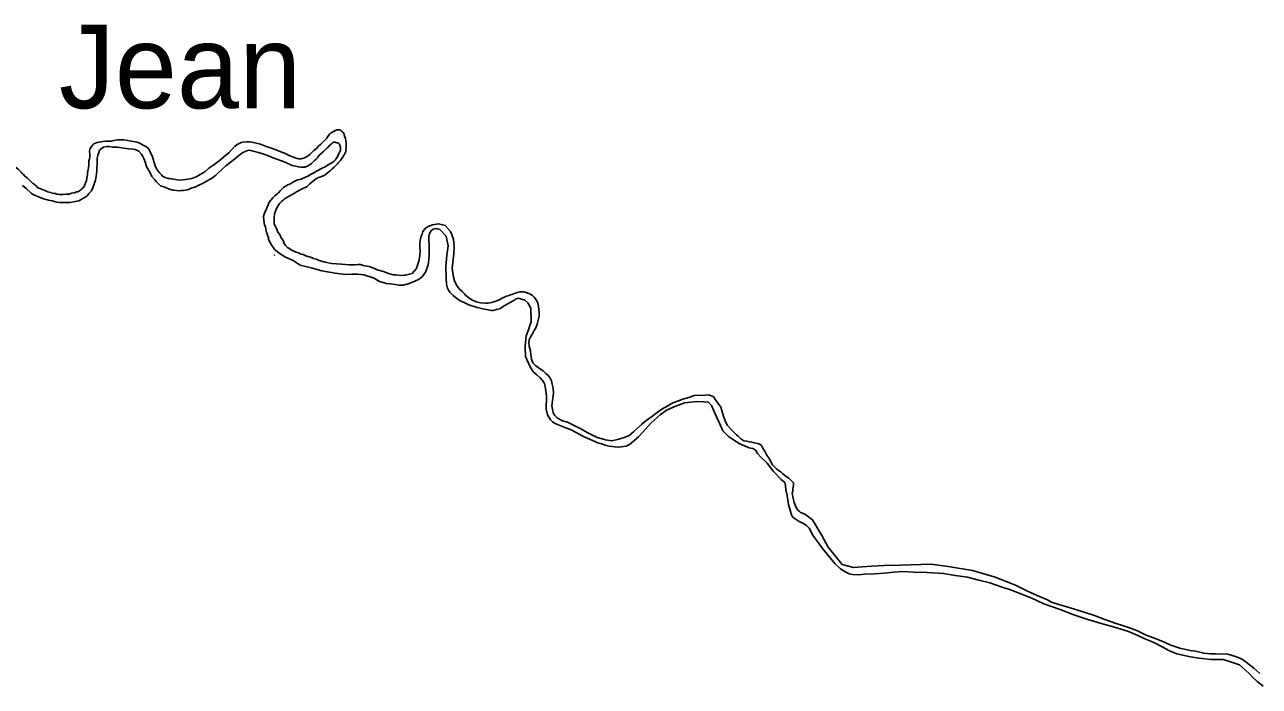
# Model space of a CAD drawing. Extents: x -83719 to 153526, y -11835 to 11446.
# Drawn here: x -3827.5 to -3567.5, y -157.2 to -17.9 of the extents above; entities that cross this region are included whole.
import ezdxf

# ---------------------------------------------------------------- set-up
doc = ezdxf.new("R2010")
doc.units = 0
doc.layers.add('Level 9', color=7, linetype='Continuous')

msp = doc.modelspace()

# ---------------------------------------------------------------- linework, layer by layer
at = {"layer": 'Level 9'}
for points in [[(-3761.85, -40.05), (-3761.95, -40.1), (-3762.21, -40.2), (-3762.61, -40.41), (-3762.88, -40.61), (-3763.17, -40.81), (-3763.34, -40.95), (-3763.7, -41.45), (-3763.93, -41.79), (-3764.19, -42.06), (-3764.59, -42.47), (-3764.95, -42.84), (-3765.25, -43.14), (-3765.65, -43.45), (-3766.18, -44.02), (-3766.66, -44.39)], [(-3761.85, -40.05), (-3761.64, -40), (-3761.41, -40), (-3761.19, -40.04), (-3760.99, -40.13), (-3760.79, -40.27), (-3760.57, -40.45), (-3760.47, -40.61), (-3760.33, -40.82), (-3760.13, -41.49), (-3760, -41.85), (-3759.89, -42.26), (-3759.85, -42.76), (-3759.84, -43.45), (-3759.85, -43.85), (-3759.9, -44.14), (-3759.92, -44.56), (-3759.99, -44.72), (-3760.11, -45.08), (-3760.31, -45.37)], [(-3773.66, -46.51), (-3775.23, -45.9), (-3776.41, -45.41), (-3777.18, -45.16), (-3778.28, -44.77), (-3779.39, -44.48), (-3779.92, -44.35), (-3780.22, -44.32), (-3780.49, -44.36), (-3780.76, -44.43), (-3781.09, -44.57), (-3781.19, -44.64), (-3781.45, -44.74), (-3781.79, -44.91), (-3781.89, -45.01), (-3782.12, -45.15), (-3783.34, -46.2), (-3783.97, -46.71), (-3785.19, -47.62), (-3785.92, -48.33), (-3787.31, -49.55), (-3788.23, -50.26), (-3789.26, -50.81), (-3789.96, -51.25), (-3791.02, -51.76), (-3791.52, -52), (-3792.25, -52.25), (-3793.25, -52.66), (-3794.11, -52.8), (-3794.68, -52.81), (-3795.08, -52.85), (-3795.58, -52.82), (-3796.35, -52.7), (-3797.25, -52.47), (-3797.99, -52.12), (-3798.96, -51.79), (-3799.84, -50.87), (-3800.21, -50.47), (-3800.76, -49.85), (-3801.03, -49.18), (-3801.34, -48.69), (-3801.47, -48.45), (-3801.78, -47.99), (-3801.95, -47.53), (-3802.19, -46.76), (-3802.47, -46.03), (-3802.74, -45.5), (-3802.91, -45.14), (-3803.52, -44.54), (-3804.29, -44.15), (-3804.69, -44.12), (-3805.59, -44.03), (-3806.7, -43.85), (-3808, -43.7), (-3809.04, -43.64), (-3809.74, -43.55), (-3810.14, -43.56), (-3810.91, -43.7), (-3811.24, -43.87), (-3811.37, -43.94), (-3811.63, -44.14), (-3811.77, -44.28), (-3811.96, -44.81), (-3812.15, -45.41), (-3812.25, -45.98), (-3812.31, -46.75), (-3812.32, -48.52), (-3812.44, -49.39), (-3812.66, -50.63), (-3813.05, -51.8), (-3813.18, -52.23), (-3813.47, -52.84), (-3814, -53.41), (-3814.33, -53.85), (-3814.69, -54.15), (-3815.06, -54.36), (-3815.49, -54.6), (-3816.12, -54.94), (-3816.52, -55.01), (-3817.18, -55.15), (-3817.98, -55.3), (-3818.72, -55.3), (-3819.52, -55.31), (-3820.19, -55.32), (-3820.75, -55.26), (-3821.79, -54.97), (-3822.53, -54.82), (-3823.57, -54.53), (-3824.07, -54.34), (-3824.61, -54.14), (-3825.24, -53.85), (-3825.68, -53.69), (-3826.15, -53.33), (-3827.2, -52.37), (-3828, -51.75)], [(-3800.08, -47.6), (-3800.7, -45.51), (-3801.08, -44.75), (-3801.22, -44.28), (-3801.63, -43.82), (-3802.03, -43.52), (-3802.7, -43.16), (-3803.31, -42.84), (-3803.84, -42.64), (-3804.68, -42.45), (-3805.88, -42.24), (-3806.68, -42.14), (-3807.32, -42.09), (-3808.02, -42.13), (-3808.75, -42.24), (-3809.32, -42.38), (-3809.59, -42.38), (-3810.49, -42.39), (-3811.05, -42.47), (-3811.49, -42.57), (-3811.95, -42.61), (-3812.29, -42.71), (-3812.98, -42.96), (-3813.21, -43.16), (-3813.48, -43.56), (-3813.74, -43.93), (-3813.87, -44.53), (-3813.79, -45.2), (-3813.85, -45.7), (-3813.92, -46.1), (-3814.01, -46.54), (-3814.03, -47.41), (-3814.13, -47.94), (-3814.16, -48.38), (-3814.32, -49.04), (-3814.31, -49.48), (-3814.44, -50.18), (-3814.53, -50.72), (-3814.72, -51.25), (-3814.86, -51.55), (-3815.05, -51.99), (-3815.41, -52.39), (-3815.64, -52.6), (-3816.01, -52.84), (-3816.24, -53.01), (-3816.44, -53.11), (-3816.64, -53.11), (-3817.04, -53.28), (-3817.2, -53.32), (-3817.67, -53.39), (-3818.2, -53.56), (-3818.8, -53.6), (-3819.5, -53.61), (-3819.74, -53.62), (-3820.31, -53.62), (-3820.74, -53.56), (-3821.08, -53.46), (-3821.41, -53.4), (-3821.71, -53.37), (-3821.98, -53.28), (-3822.05, -53.24), (-3822.72, -53.05), (-3822.82, -52.99)], [(-3773.24, -44.77), (-3775.12, -44), (-3776.46, -43.58), (-3777.87, -43.06), (-3778.77, -42.84), (-3779.68, -42.58), (-3780.21, -42.56), (-3780.68, -42.53), (-3781.58, -42.61), (-3781.98, -42.71), (-3782.48, -42.95), (-3783.27, -43.46), (-3784.46, -44.81), (-3785.22, -45.42), (-3786.61, -46.54), (-3787.67, -47.42), (-3788.79, -48.1), (-3789.62, -48.84), (-3790.55, -49.46), (-3791.31, -49.83), (-3792.31, -50.24), (-3793.21, -50.42), (-3794.14, -50.53), (-3794.97, -50.61), (-3796.18, -50.43), (-3796.64, -50.36), (-3796.98, -50.3), (-3797.33, -50.24)], [(-3761.03, -44.26), (-3761, -43.72), (-3761.07, -43.56), (-3761.07, -43.46), (-3761.18, -43.23), (-3761.28, -42.99), (-3761.31, -42.96), (-3761.45, -42.86), (-3761.55, -42.76), (-3761.78, -42.73), (-3762.02, -42.67), (-3762.19, -42.64), (-3762.35, -42.64), (-3762.52, -42.64), (-3762.72, -42.74), (-3762.95, -42.95), (-3763.21, -43.18), (-3763.35, -43.35), (-3763.64, -43.66), (-3763.94, -43.96), (-3764.17, -44.16), (-3764.57, -44.53), (-3764.8, -44.74), (-3764.96, -44.91), (-3765.36, -45.24), (-3765.52, -45.45), (-3765.79, -45.75), (-3765.85, -45.88), (-3766.08, -46.12), (-3766.18, -46.22), (-3766.51, -46.49), (-3766.61, -46.63), (-3767.01, -46.97), (-3767.14, -47.1), (-3767.44, -47.31), (-3767.7, -47.48), (-3767.86, -47.58)], [(-3770.84, -47.6), (-3771.18, -47.52), (-3771.51, -47.42), (-3771.81, -47.26), (-3771.88, -47.19), (-3772.22, -47.1), (-3772.38, -47), (-3772.92, -46.77), (-3773.22, -46.64), (-3773.46, -46.58), (-3773.66, -46.51)], [(-3771.12, -45.72), (-3771.16, -45.72), (-3771.46, -45.59), (-3771.67, -45.49), (-3772.14, -45.26), (-3772.27, -45.23), (-3772.57, -45.07), (-3772.81, -44.94), (-3773.24, -44.77)], [(-3766.66, -44.39), (-3766.98, -44.73), (-3767.42, -45.15), (-3767.85, -45.48), (-3768.31, -45.77), (-3768.6, -45.9), (-3768.85, -45.96), (-3769.34, -46.11), (-3769.64, -46.12), (-3769.86, -46.11), (-3770.16, -46.06), (-3770.56, -45.92), (-3771.12, -45.72)], [(-3760.89, -46.26), (-3761.13, -46.55), (-3761.45, -46.92), (-3761.64, -47.15), (-3762.01, -47.5), (-3762.35, -47.85), (-3762.79, -48.26), (-3763.22, -48.66), (-3763.53, -48.92)], [(-3763.29, -47.21), (-3763, -47.02), (-3762.8, -46.92), (-3762.57, -46.75), (-3762.37, -46.61), (-3762.11, -46.31), (-3761.91, -46.04), (-3761.85, -45.97), (-3761.62, -45.57), (-3761.46, -45.16), (-3761.23, -44.73), (-3761.13, -44.63), (-3761.1, -44.46), (-3761.03, -44.26)], [(-3760.89, -46.26), (-3760.78, -46.02), (-3760.38, -45.48), (-3760.31, -45.37)], [(-3825.5, -51.53), (-3825.87, -51.22), (-3826.24, -50.89), (-3826.45, -50.69), (-3826.62, -50.56), (-3827.05, -50.13), (-3827.49, -49.77), (-3827.8, -49.41), (-3827.97, -49.21), (-3828.17, -49.11), (-3828.44, -48.85), (-3828.44, -48.82), (-3828.88, -48.35), (-3829.21, -48.09), (-3829.58, -47.82)], [(-3800.08, -47.6), (-3800.02, -47.76), (-3799.93, -47.94), (-3799.72, -48.33), (-3799.45, -48.72), (-3799.05, -49.11), (-3798.75, -49.53), (-3798.42, -49.84), (-3797.98, -50.03), (-3797.33, -50.24)], [(-3770.84, -47.6), (-3770.42, -47.69), (-3769.9, -47.83), (-3769.39, -47.91), (-3769.01, -47.88), (-3768.61, -47.86), (-3768.49, -47.83), (-3768.31, -47.78), (-3767.86, -47.58)], [(-3770.27, -53.06), (-3770.01, -52.91), (-3769.22, -52.53), (-3768.05, -51.95), (-3767.53, -51.44), (-3767.06, -51.04), (-3766.27, -50.43), (-3766.17, -50.33), (-3766.04, -50.26), (-3765.77, -50.15), (-3765.71, -50.09), (-3765.37, -49.98), (-3764.81, -49.81), (-3764.31, -49.54), (-3763.75, -49.1), (-3763.53, -48.92)], [(-3763.29, -47.21), (-3763.74, -47.49), (-3764.28, -47.79), (-3764.86, -48.08), (-3765.3, -48.32), (-3765.66, -48.5), (-3766.09, -48.74), (-3766.76, -49.14), (-3767.2, -49.35), (-3767.56, -49.57)], [(-3825.5, -51.53), (-3825.13, -51.8), (-3824.97, -51.99), (-3824.6, -52.27), (-3824.29, -52.38), (-3824.02, -52.52), (-3823.62, -52.68), (-3823.4, -52.73)], [(-3774.9, -65.25), (-3774.95, -65.18), (-3775.01, -65.05), (-3775.25, -64.65), (-3775.52, -64.39), (-3775.8, -63.92), (-3775.97, -63.52), (-3776.17, -63.06), (-3776.21, -62.73), (-3776.42, -62.2), (-3776.56, -61.7), (-3776.66, -61.43), (-3776.73, -60.87), (-3776.84, -60.47), (-3777.01, -60.07), (-3777.19, -59.04), (-3777.23, -58.27), (-3777, -57.57), (-3776.61, -56.69), (-3776.26, -55.79), (-3776.03, -55.28), (-3775.3, -54.37), (-3774.84, -53.94), (-3774.34, -53.53), (-3774.11, -53.26), (-3773.75, -52.89), (-3773.39, -52.52), (-3773.03, -52.18), (-3772.13, -51.6), (-3771.4, -51.29), (-3771.1, -51.05), (-3770.47, -50.75), (-3770.07, -50.57), (-3769.57, -50.47), (-3769.14, -50.33), (-3768.41, -50.02), (-3767.91, -49.81), (-3767.56, -49.57)], [(-3822.82, -52.99), (-3823.29, -52.79), (-3823.4, -52.73)], [(-3770.27, -53.06), (-3770.7, -53.34), (-3771.24, -53.65), (-3771.97, -54.05), (-3772.5, -54.32), (-3772.84, -54.58), (-3773.12, -54.8), (-3773.45, -55.1), (-3773.67, -55.32), (-3773.85, -55.55)], [(-3765.51, -67.53), (-3766.11, -67.28), (-3766.68, -67.12), (-3767.15, -66.92), (-3767.65, -66.79), (-3768.32, -66.53), (-3768.49, -66.47), (-3768.89, -66.27), (-3769.33, -66.18), (-3769.9, -65.92), (-3770.33, -65.79), (-3770.84, -65.6), (-3770.94, -65.5), (-3771.34, -65.34), (-3771.91, -64.94), (-3772.18, -64.78), (-3772.59, -64.38), (-3772.86, -63.95), (-3773.13, -63.36), (-3773.57, -62.63), (-3773.71, -62.2), (-3774.12, -61.67), (-3774.29, -61.4), (-3774.46, -60.94), (-3774.73, -60.41), (-3774.97, -59.88), (-3775.01, -59.21), (-3775.02, -58.58), (-3774.9, -57.74), (-3774.61, -56.74), (-3774.25, -56.13), (-3773.85, -55.55)], [(-3721.33, -84.88), (-3721.27, -84.28), (-3720.95, -83.57), (-3720.43, -82.73), (-3720.24, -82.26), (-3719.82, -81.58), (-3719.59, -80.94), (-3719.15, -79.3), (-3719.2, -78.53), (-3719.25, -77.76), (-3719.36, -76.79), (-3719.5, -76.33), (-3719.95, -75.6), (-3720.26, -75.24), (-3720.6, -74.88), (-3721.17, -74.58), (-3721.54, -74.39), (-3722.11, -74.2), (-3722.51, -74.14), (-3723.18, -74.12), (-3723.54, -74.19), (-3724.04, -74.33), (-3724.73, -74.61), (-3725.4, -74.86), (-3725.53, -74.89), (-3726.06, -75.07), (-3726.99, -75.45), (-3727.61, -75.83), (-3728.08, -76.04), (-3728.71, -76.28), (-3729.21, -76.36), (-3729.9, -76.51), (-3730.54, -76.52), (-3731.44, -76.47), (-3732.48, -76.25), (-3733.35, -75.83), (-3734.06, -75.34), (-3734.63, -74.92), (-3734.94, -74.55), (-3735.38, -74.09), (-3735.99, -73.57), (-3736.47, -72.94), (-3736.81, -72.31), (-3737.05, -71.82), (-3737.2, -71.02), (-3737.5, -69.15), (-3737.18, -66.17), (-3737.11, -64.56), (-3737.2, -63.03), (-3737.86, -61.43), (-3738.98, -60.15), (-3740.42, -59.81), (-3741.62, -60.03), (-3742.58, -60.38), (-3743.17, -60.79), (-3743.66, -61.43), (-3743.85, -61.97), (-3744.01, -62.41), (-3744.26, -63.35), (-3744.35, -63.99), (-3744.3, -64.89), (-3744.26, -65.42), (-3744.31, -66.56), (-3744.52, -67.7), (-3744.78, -68.51), (-3745.03, -69.21), (-3745.49, -69.82), (-3745.95, -70.26), (-3747.31, -70.62), (-3747.64, -70.66), (-3748.41, -70.71), (-3749.31, -70.59), (-3749.88, -70.53), (-3750.95, -70.28), (-3751.96, -69.86), (-3753.3, -69.49), (-3754.04, -69.17), (-3755.01, -68.81), (-3756.25, -68.57), (-3756.78, -68.38), (-3757.38, -68.35), (-3757.99, -68.42)], [(-3721.44, -82.14), (-3721.15, -81.24), (-3720.9, -80.46), (-3720.95, -77.59), (-3721.54, -76.43), (-3722.18, -75.87), (-3723.62, -75.5), (-3724.15, -75.71), (-3724.41, -75.91), (-3725.54, -76.56), (-3726.39, -77.01), (-3726.89, -77.29), (-3727.35, -77.63), (-3727.91, -77.81), (-3728.91, -78.09), (-3729.28, -78.07), (-3730.28, -77.88), (-3731.08, -77.7), (-3732.26, -77.45), (-3734, -76.91), (-3734.87, -76.49), (-3735.81, -76.01), (-3736.49, -75.55), (-3737.3, -74.93), (-3738.01, -74.24), (-3738.29, -73.78), (-3738.49, -73.34), (-3738.71, -72.51), (-3738.79, -71.31), (-3738.84, -68.77), (-3738.61, -66.43), (-3738.38, -64.42), (-3738.78, -62.39), (-3740.07, -61), (-3740.64, -60.85), (-3740.94, -60.82), (-3741.54, -60.96), (-3741.87, -61.2), (-3742.19, -61.61), (-3742.22, -61.81), (-3742.35, -62.15), (-3742.41, -62.38), (-3742.44, -62.82), (-3742.34, -64.82), (-3742.35, -66.22), (-3742.43, -67.43), (-3742.58, -68.43), (-3743.15, -70.01), (-3743.84, -71), (-3744.63, -71.51), (-3745.85, -72.1), (-3746.74, -72.45), (-3747.84, -72.74), (-3748.71, -72.75), (-3749.54, -72.63), (-3750.55, -72.48), (-3751.35, -72.36), (-3752.82, -71.95), (-3753.19, -71.72), (-3753.97, -71.27), (-3754.77, -70.98), (-3755.51, -70.79), (-3756.11, -70.57), (-3756.68, -70.48), (-3757.48, -70.43), (-3758.62, -70.41)], [(-3775, -66.47), (-3774.93, -66.42)], [(-3774.93, -66.42), (-3774.87, -66.38)], [(-3758.62, -70.41), (-3759.91, -70.46), (-3762.14, -70.2), (-3764.94, -69.73), (-3767.22, -69.06), (-3769.51, -68.49), (-3771.01, -67.55), (-3772.62, -66.83), (-3773.76, -66.15), (-3774.9, -65.25)], [(-3757.99, -68.42), (-3759.13, -68.43), (-3760.84, -68.28), (-3762.92, -68.18), (-3764.27, -67.92), (-3765.51, -67.53)], [(-3595.09, -145.69), (-3597.98, -144.8), (-3600.52, -144.08), (-3603.64, -143.16), (-3606.59, -142.21), (-3609.44, -141.06), (-3612.86, -139.84), (-3615.28, -138.75), (-3617.73, -137.75), (-3619.92, -136.92), (-3621.66, -136.38), (-3624.24, -135.46), (-3626.59, -134.86), (-3629, -134.24), (-3631.54, -133.88), (-3634.01, -133.45), (-3637.45, -133.28), (-3640.32, -133.16), (-3642.49, -133.06), (-3644.45, -133.17), (-3646.52, -133.37), (-3648.45, -133.57), (-3650.68, -133.64), (-3651.88, -133.73), (-3653.18, -133.68), (-3653.88, -133.56), (-3654.32, -133.33), (-3654.93, -132.98), (-3655.74, -132.46), (-3656.92, -131.37), (-3659.54, -128.18), (-3661.52, -125.4), (-3662.32, -123.91), (-3662.89, -123.39), (-3663.67, -122.87), (-3664.44, -122.51), (-3665.45, -121.83), (-3665.86, -121.43), (-3666.13, -120.9), (-3666.35, -120.1), (-3666.67, -118.94), (-3666.93, -117.01), (-3667.22, -115.87), (-3667.27, -114.97), (-3667.45, -114.31), (-3668.22, -113.69), (-3669.85, -111.98), (-3671.18, -110.26), (-3672.4, -109.01), (-3673.22, -108.16), (-3673.56, -107.59), (-3673.66, -107.43), (-3674.17, -107.17), (-3674.94, -106.98), (-3676.95, -106.18), (-3678.47, -105.17), (-3679.28, -104.62), (-3680.53, -103.4), (-3681.23, -101.78), (-3681.82, -100.45), (-3682.37, -99.22), (-3682.86, -98.09), (-3683.5, -97.4), (-3684.54, -97.29), (-3685.97, -97.24), (-3688.57, -97.52), (-3690.96, -98.4), (-3692.34, -99.06), (-3693.73, -100.02), (-3695.57, -101.72), (-3696.81, -103.08), (-3698.29, -104.68), (-3699.3, -105.63), (-3700.13, -106.28), (-3700.85, -106.62), (-3702.45, -106.89), (-3703.15, -106.8), (-3704.45, -106.62), (-3705.26, -106.43), (-3706.06, -106.18), (-3706.83, -105.92), (-3709.69, -104.67), (-3712.45, -103.21), (-3713.59, -102.76), (-3715.7, -101.93), (-3716.34, -101.54), (-3716.82, -101.12), (-3717.4, -100.02), (-3717.72, -98.86), (-3717.64, -96.15), (-3717.86, -94.48), (-3718.05, -93.48), (-3718.49, -92.82), (-3718.97, -92.23), (-3719.68, -91.64), (-3720.46, -90.98), (-3721.18, -89.83), (-3722.08, -87.77), (-3722.15, -85.56), (-3721.92, -83.42), (-3721.44, -82.14)], [(-3665.87, -116.58), (-3665.78, -116.12), (-3665.72, -115.68), (-3665.7, -115.21), (-3665.6, -114.78), (-3665.64, -114.34), (-3665.88, -114.08), (-3666.22, -113.72), (-3666.63, -113.36), (-3667.13, -113.03), (-3667.51, -112.77), (-3667.91, -112.44), (-3668.28, -112.08), (-3668.59, -111.89), (-3669.13, -111.5), (-3669.57, -111.07), (-3670.01, -110.57), (-3670.73, -109.25), (-3671.21, -108.52), (-3671.52, -107.96), (-3672.07, -107.07), (-3672.35, -106.54), (-3672.65, -106.27), (-3673.15, -106.08), (-3673.92, -105.96), (-3674.39, -105.84), (-3674.89, -105.74), (-3675.46, -105.62), (-3676.06, -105.53), (-3676.7, -105.14), (-3677.28, -104.55), (-3677.65, -104.29), (-3678.7, -103.2), (-3679.59, -102.25), (-3680.04, -101.32), (-3680.42, -100.12), (-3680.67, -99.39), (-3680.95, -98.43), (-3681.46, -97.67), (-3682.04, -96.88), (-3682.39, -96.31), (-3682.42, -96.25), (-3683.43, -95.83), (-3684.1, -95.88), (-3686.56, -95.98), (-3687.69, -96.37), (-3688.92, -96.76), (-3689.84, -97.11), (-3691.04, -97.53), (-3692.09, -98.12), (-3693.32, -98.84), (-3694.04, -99.32), (-3695.49, -100.48), (-3696.12, -100.89), (-3697.04, -101.58), (-3697.66, -102.09), (-3698.58, -103.01), (-3699.27, -103.56), (-3699.8, -104.03), (-3700.26, -104.37), (-3701.05, -104.72), (-3702.41, -105.21), (-3703.91, -105.51), (-3705.18, -105.29), (-3705.91, -105.11), (-3706.99, -104.79), (-3709.07, -103.79), (-3710.38, -103.01), (-3711.8, -102.27), (-3713.21, -101.62), (-3714.28, -101.34), (-3715.29, -100.72), (-3715.87, -100.16), (-3716.21, -99.63), (-3716.32, -99.2), (-3716.43, -98.54), (-3716.5, -98.14), (-3716.15, -95.52), (-3716.23, -94.42), (-3716.44, -93.59), (-3716.59, -92.86), (-3716.94, -92.19), (-3717.31, -91.73), (-3717.75, -91.31), (-3718.33, -90.81), (-3719.14, -90.26), (-3719.95, -89.64), (-3720.49, -89.11), (-3720.83, -88.35), (-3720.95, -87.42), (-3721.03, -86.58), (-3721.28, -85.58), (-3721.33, -84.88)], [(-3664.16, -120.63), (-3664.42, -120.37), (-3664.81, -120.01), (-3665.17, -119.2), (-3665.45, -118.55), (-3665.69, -117.7), (-3665.87, -116.58)], [(-3567.37, -154.57), (-3568.65, -153.42), (-3570.28, -152.18), (-3571.29, -151.46), (-3572.5, -150.98), (-3574.11, -150.44), (-3576.74, -150.42), (-3577.77, -150.37), (-3579.21, -150.26), (-3580.85, -149.86), (-3582.05, -149.68), (-3584.23, -149.21), (-3586.11, -148.54), (-3587.85, -147.8), (-3589.8, -147), (-3591.31, -146.46), (-3593.19, -145.52), (-3594.6, -145.01), (-3595.91, -144.57), (-3597.86, -143.93), (-3600.04, -143.17), (-3602.25, -142.3), (-3604.2, -141.67), (-3606.41, -140.97), (-3608.02, -140.5), (-3609.53, -140.05), (-3611.27, -139.48), (-3612.14, -139.03), (-3613.79, -138.29), (-3615.57, -137.55), (-3616.61, -137.03), (-3618.83, -135.9), (-3623.16, -134.27), (-3625.71, -133.48), (-3627.89, -132.85), (-3633.04, -131.97), (-3636.68, -131.49), (-3643.08, -131.7), (-3646.61, -131.77), (-3649.11, -131.94), (-3651.14, -132.08), (-3653.01, -132.18), (-3655.38, -131.58), (-3658.28, -127.95), (-3659.62, -125.47), (-3661.64, -122.2), (-3662.42, -121.51), (-3663.23, -120.95), (-3663.74, -120.79), (-3664.16, -120.63)], [(-3566.66, -157.23), (-3567.94, -156.19), (-3568.96, -155.3), (-3569.67, -154.51), (-3571.67, -152.74), (-3573.34, -152.17), (-3575.15, -151.6), (-3577.62, -151.57), (-3580.26, -151.28), (-3582.03, -151.01), (-3584.91, -150.39), (-3586.56, -149.72), (-3587.8, -148.97), (-3589.89, -147.91), (-3591.63, -147.23), (-3593.11, -146.52), (-3595.09, -145.69)]]:
    msp.add_lwpolyline(points, dxfattribs=at)

# ---------------------------------------------------------------- texts
msp.add_text('Jean', height=17.6, dxfattribs=at).set_placement((-3820.33, -35.47))

doc.saveas('drawing.dxf')
